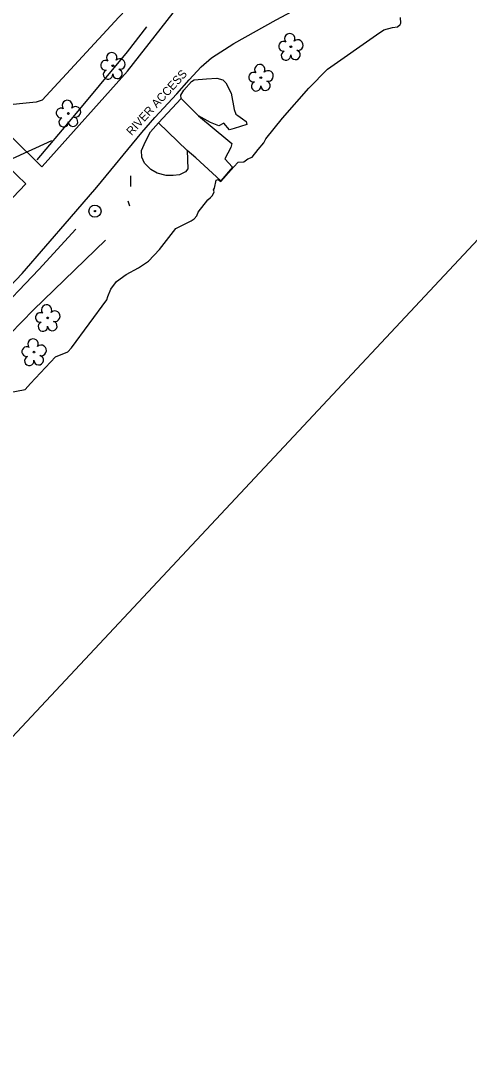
# Model space of a CAD drawing. Extents: x 1645945 to 2447332, y 713118 to 970361.
# Drawn here: x 1647816.3 to 1647977.1, y 969521.4 to 969891.3 of the extents above; entities that cross this region are included whole.
import ezdxf

# ---------------------------------------------------------------- set-up
doc = ezdxf.new("R2010")
doc.units = 0
for name, color, linetype in [('Exist Hydro Jurisdictional Stream or Body of Water', 7, 'Continuous'), ('Exist Other Culture Area Outline', 7, 'Continuous'), ('Exist Other Culture Area Outline Text', 7, 'Continuous'), ('Exist Other Culture Fence Line', 7, 'Continuous'), ('Exist Other Culture Fence Line Leader', 7, 'Continuous'), ('Exist Other Culture Located Object CELL', 7, 'Continuous'), ('Exist Other Culture Sign CELL', 7, 'Continuous'), ('Exist Property Line', 7, 'Continuous'), ('Exist Roads Soil', 7, 'Continuous'), ('Exist Vegetation Tree CELL', 7, 'Continuous'), ('Exist Vegetation Woods Line', 7, 'Continuous')]:
    doc.layers.add(name, color=color, linetype=linetype)

msp = doc.modelspace()

# ---------------------------------------------------------------- linework, layer by layer
at = {"layer": 'Exist Hydro Jurisdictional Stream or Body of Water'}
for points in [[(1647847.24, 969791.3), (1647847.61, 969792.48), (1647848.61, 969795.18), (1647850.63, 969797.84), (1647854.12, 969800.36), (1647858.62, 969802.82), (1647862.17, 969805.15), (1647866.12, 969809.38), (1647871.99, 969816.92), (1647874.3, 969818.08), (1647877.41, 969819.57), (1647878.47, 969820.27), (1647879.46, 969821.4), (1647879.89, 969822.68), (1647883.44, 969827.1), (1647884.33, 969828), (1647885.06, 969828.64), (1647885.66, 969829.94), (1647885.39, 969830.74), (1647885.78, 969831.35), (1647886.36, 969834.19), (1647887.11, 969834.47), (1647888.05, 969833.73), (1647892.66, 969838.93), (1647894.32, 969840.59), (1647896.31, 969840.79), (1647897.79, 969841.8), (1647899.32, 969842.46), (1647901.49, 969845.16), (1647903.45, 969847.56), (1647904.21, 969848.92), (1647910.19, 969856.4), (1647919.54, 969867.13), (1647926.25, 969873.94), (1647943.81, 969886.21), (1647946.46, 969888.01), (1647949.52, 969888.87), (1647951.37, 969889.15), (1647952.25, 969889.93), (1647952.53, 969890.44), (1647952.46, 969892.39)], [(1647812.33, 969758.15), (1647818.01, 969759.19), (1647819.87, 969761.35), (1647828.88, 969770.85), (1647833.3, 969772.7), (1647834.6, 969774.07), (1647847.24, 969791.3)]]:
    msp.add_lwpolyline(points, dxfattribs=at)
at = {"layer": 'Exist Other Culture Area Outline'}
for points in [[(1647873.83, 969863.4), (1647873.76, 969864.62), (1647874.76, 969866.45), (1647877.54, 969869.56), (1647878.56, 969870.1), (1647882.97, 969870.46), (1647886.65, 969870.76), (1647888.8, 969870.09), (1647889.8, 969869.02), (1647891.72, 969865.36), (1647892.8, 969859.5), (1647893.41, 969857.87), (1647894.17, 969857.28), (1647895.84, 969856.18), (1647897.18, 969855.21), (1647897.41, 969854.1), (1647892.78, 969852.62), (1647891.14, 969852.19), (1647889.08, 969854.56), (1647887.35, 969853.64), (1647884.37, 969854.88), (1647880, 969857.25)], [(1647875.98, 969844.85), (1647876.26, 969838.26), (1647875.45, 969837.14), (1647873.21, 969836.09), (1647870.97, 969835.84), (1647868.42, 969835.8), (1647865.3, 969836.71), (1647862.93, 969837.94), (1647860.77, 969840.27), (1647859.79, 969842.42), (1647859.65, 969844.79), (1647861.02, 969848.06), (1647862.84, 969851.53), (1647865.71, 969854.69)]]:
    msp.add_lwpolyline(points, dxfattribs=at)
msp.add_lwpolyline([(1647865.71, 969854.69), (1647873.83, 969863.4), (1647880, 969857.25), (1647890.62, 969848.47), (1647891.98, 969847.33), (1647891.61, 969845.84), (1647889.44, 969841.8), (1647892.24, 969838.83), (1647888.05, 969833.97), (1647879.06, 969842.13), (1647875.98, 969844.85)], close=True, dxfattribs=at)
at = {"layer": 'Exist Other Culture Fence Line'}
for points in [[(1647822.23, 969841.45), (1647834.52, 969856.08), (1647854.6, 969880.16), (1647861.55, 969889.11)], [(1647836.14, 969816.64), (1647822.8, 969802.2), (1647806.1, 969784.74), (1647789.66, 969768.09), (1647773.88, 969750.97), (1647757.53, 969733.44), (1647745.42, 969719.82), (1647732.73, 969705.92), (1647724.99, 969696.36), (1647715.08, 969683.63), (1647696.29, 969661.16), (1647688.81, 969652.14), (1647674.62, 969634.09), (1647646.6, 969611.84)], [(1647651.93, 969606.23), (1647662.05, 969613.58), (1647671.87, 969620.9), (1647679.68, 969627.22), (1647689.25, 969637.47), (1647700.19, 969651.24), (1647715.02, 969669.5), (1647729.67, 969687.53), (1647754.77, 969719.94), (1647766.77, 969733.37), (1647775.43, 969741.53), (1647783.81, 969750.03), (1647800.17, 969766.99), (1647808.26, 969774.85), (1647820.92, 969787.78), (1647846.68, 969812.64)]]:
    msp.add_lwpolyline(points, dxfattribs=at)
at = {"layer": 'Exist Other Culture Fence Line Leader'}
msp.add_lwpolyline([(1647827.43, 969848.22), (1647804.53, 969837.88), (1647791.71, 969825.2)], dxfattribs=at)
at = {"layer": 'Exist Other Culture Located Object CELL'}
for radius in [2.18, 0.24]:
    msp.add_circle((1647842.96, 969823.08), radius, dxfattribs=at)
at = {"layer": 'Exist Other Culture Sign CELL'}
for p, q in [((1647855.73, 969835.73), (1647855.66, 969831.87)), ((1647854.75, 969826.72), (1647855.35, 969824.95))]:
    msp.add_line(p, q, dxfattribs=at)
at = {"layer": 'Exist Property Line'}
msp.add_line((1647312.95, 969100.34), (1648195.03, 970042.45), dxfattribs=at)
at = {"layer": 'Exist Roads Soil'}
for points in [[(1647825.16, 969840.29), (1647854.68, 969873.27), (1647878.69, 969904.08), (1647887.29, 969918.9), (1647894, 969947.84), (1647897.55, 969963.48), (1647897.73, 969964.36), (1647898, 969965.01), (1647899.35, 969966.38), (1647936.25, 969999.54), (1647950.33, 970011.39), (1647950.78, 970011.69)], [(1647833.9, 969820.27), (1647843.63, 969831.63), (1647859.7, 969851.23), (1647864.42, 969856.65), (1647872.24, 969865.05), (1647876.68, 969870.11), (1647881, 969874.71), (1647884.73, 969878.03), (1647892.67, 969883.14), (1647907.86, 969891.64), (1647915.49, 969895.7), (1647918.11, 969897.01), (1647926.28, 969902.5), (1647945.52, 969921.1), (1647969.9, 969945.49), (1647987.24, 969963.4), (1648002.75, 969980.2), (1648005.41, 969983.22)], [(1647812.7, 969850), (1647823.96, 969838.96)], [(1647811.28, 969825.55), (1647818.19, 969832.9), (1647808.35, 969842.22)], [(1647823.96, 969838.96), (1647825.16, 969840.29)], [(1647799, 969781.99), (1647816.85, 969800.78), (1647833.9, 969820.27)]]:
    msp.add_lwpolyline(points, dxfattribs=at)
at = {"layer": 'Exist Vegetation Tree CELL'}
for p, q in [((1647913.11, 969881.96), (1647913.11, 969881.96)), ((1647849.34, 969875.17), (1647849.34, 969875.17)), ((1647902.41, 969870.89), (1647902.41, 969870.89)), ((1647833.43, 969858.05), (1647833.43, 969858.05)), ((1647826.02, 969784.83), (1647826.02, 969784.83)), ((1647821.13, 969772.6), (1647821.13, 969772.6))]:
    msp.add_line(p, q, dxfattribs=at)
for centre in [(1647913.11, 969881.96), (1647849.34, 969875.17), (1647902.41, 969870.89), (1647833.43, 969858.05), (1647826.02, 969784.83), (1647821.13, 969772.6)]:
    msp.add_circle(centre, 0.326, dxfattribs=at)
for centre, radius, start, end in [((1647912.73, 969884.84), 1.86, 330.1651, 219.7134), ((1647915.66, 969882.55), 1.9, 257.1011, 134.1999), ((1647910.51, 969882.12), 1.73, 62.6636, 279.3457), ((1647911.41, 969878.84), 1.69, 111.5671, 6.231), ((1647914.78, 969879.06), 1.7, 181.2822, 74.56), ((1647846.73, 969875.32), 1.73, 62.6636, 279.3457), ((1647848.95, 969878.04), 1.86, 330.1651, 219.7134), ((1647851.89, 969875.76), 1.9, 257.1011, 134.1999), ((1647847.63, 969872.05), 1.69, 111.5671, 6.231), ((1647851.01, 969872.27), 1.7, 181.2822, 74.56), ((1647902.02, 969873.77), 1.86, 330.1651, 219.7134), ((1647904.96, 969871.48), 1.9, 257.1011, 134.1999), ((1647899.8, 969871.05), 1.73, 62.6636, 279.3457), ((1647900.7, 969867.77), 1.69, 111.5671, 6.231), ((1647904.08, 969867.99), 1.7, 181.2822, 74.56), ((1647833.04, 969860.92), 1.86, 330.1651, 219.7134), ((1647830.82, 969858.2), 1.73, 62.6636, 279.3457), ((1647835.98, 969858.63), 1.9, 257.1011, 134.1999), ((1647831.72, 969854.92), 1.69, 111.5671, 6.231), ((1647835.1, 969855.15), 1.7, 181.2822, 74.56), ((1647825.63, 969787.7), 1.86, 330.1651, 219.7134), ((1647823.41, 969784.98), 1.73, 62.6636, 279.3457), ((1647828.56, 969785.42), 1.9, 257.1011, 134.1999), ((1647824.31, 969781.71), 1.69, 111.5671, 6.231), ((1647827.69, 969781.93), 1.7, 181.2822, 74.56), ((1647820.75, 969775.48), 1.86, 330.1651, 219.7134), ((1647818.53, 969772.76), 1.73, 62.6636, 279.3457), ((1647823.68, 969773.19), 1.9, 257.1011, 134.1999), ((1647819.43, 969769.48), 1.69, 111.5671, 6.231), ((1647822.81, 969769.7), 1.7, 181.2822, 74.56)]:
    msp.add_arc(centre, radius, start, end, dxfattribs=at)
at = {"layer": 'Exist Vegetation Woods Line'}
msp.add_lwpolyline([(1647824.83, 970077.33), (1647839.22, 969978.28), (1647855.08, 969897.94), (1647854.31, 969895.44), (1647851.54, 969892.5), (1647824.08, 969862.82), (1647821.91, 969862.11), (1647808.81, 969860.85), (1647791.79, 969849.82), (1647790.19, 969849.9), (1647792.99, 969876.68), (1647792.7, 969877.05), (1647782.35, 969886.2), (1647760.24, 969905.93), (1647750.48, 969913.52), (1647750.47, 969913.55), (1647746.78, 969914.04), (1647739.49, 969914.41), (1647738.63, 969915.59), (1647738.2, 969917.48), (1647770.38, 969971.84), (1647786.35, 970008.59), (1647806.57, 970059.22), (1647816.29, 970081.77)], dxfattribs=at)

# ---------------------------------------------------------------- texts
at = {"layer": 'Exist Other Culture Area Outline Text'}
msp.add_text('RIVER ACCESS', height=3, rotation=47.694, dxfattribs=at).set_placement((1647856.11, 969849.96))

doc.saveas('drawing.dxf')
